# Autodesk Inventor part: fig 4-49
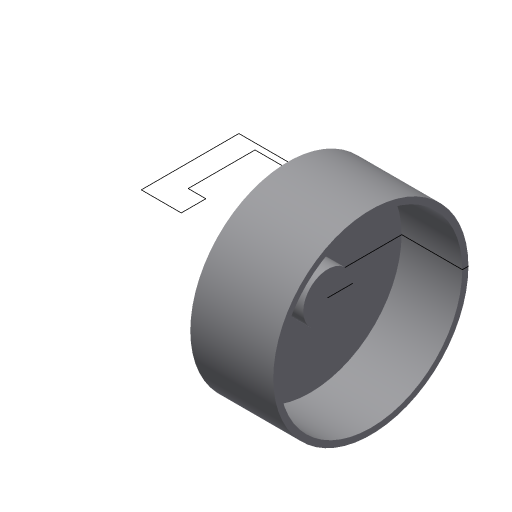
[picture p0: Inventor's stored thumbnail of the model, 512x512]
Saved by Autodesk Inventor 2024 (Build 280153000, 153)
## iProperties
Created: 2004-05
Part Number: fig 4-49
Document SubType Name: Modeling
Designer: CADCIM Technologies
Manufacturer: Standard
Standards Organization: Custom
Density: 1 g/cm^3
Material: Generic
Appearance: Default
Author: CADCIM Technologies
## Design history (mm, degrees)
sketch "Sketch1"
  geometry: L1 (37.08, 12.209)-(23.643, 12.209); L2 (23.643, 12.209)-(23.643, 45.026); L3 (23.643, 45.026)-(51.55, 45.026); L4 (51.55, 45.026)-(51.55, 42.959); L5 (51.55, 42.959)-(31.137, 42.959); L6 (31.137, 42.959)-(31.137, 20.478); L7 (31.137, 20.478)-(37.08, 20.478); L8 (37.08, 20.478)-(37.08, 12.209); L9 (86.437, 12.209)-(73, 12.209); L10 (73, 12.209)-(73, 45.026); L11 (73, 45.026)-(100.907, 45.026); L12 (100.907, 45.026)-(100.907, 42.959); L13 (100.907, 42.959)-(80.494, 42.959); L14 (80.494, 42.959)-(80.494, 20.478); L15 (80.494, 20.478)-(86.437, 20.478); L16 (86.437, 20.478)-(86.437, 12.209)
  constraints: 32 end point, 12 parallel, 2 horizontal, 2 perpendicular
revolve "Revolution1" sketch "Sketch1" stored, may be unused: angle "d0" = 90 deg
body "Solid1"
